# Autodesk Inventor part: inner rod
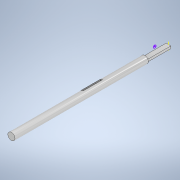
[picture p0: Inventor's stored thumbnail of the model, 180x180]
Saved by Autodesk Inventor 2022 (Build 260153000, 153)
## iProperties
Created: 2021-06
Part Number: inner rod
Material: Aluminum 6061-AHC
Document SubType Name: Modeling
Designer: adams
Density: 2.7 g/cm^3
Appearance: Aluminum - Dark
Author: adams
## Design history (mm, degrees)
sketch "Sketch1"
  geometry: 1 further point
sketch "Sketch2"
  geometry: C1 r 19.05 at (0, 0); 1 further point
  constraints: 1 centre point, 1 coincident
  dimensions: "d0" = 38.1 diameter of C1
extrude "Extrusion1" new body sketch "Sketch2" distance "d1" = 711.2; taper "d2" = 0 deg
sketch "Sketch3"
  geometry: L1 (0, 1753.937)-(0, 3144.253); L2 (0, 3144.253)-(101.6, 3144.253); L3 (101.6, 3144.253)-(101.6, 1753.937); L4 (101.6, 1753.937)-(0, 1753.937); L5 (-19.05, 0)-(-19.05, 711.2) reference; L6 (0, 225.423)-(0, 328.216); L7 (0, 328.216)-(13.075, 328.216); L8 (13.075, 328.216)-(13.075, 225.423); L9 (13.075, 225.423)-(0, 225.423); L10 (19.05, 0)-(19.05, 711.2) reference; 1 further point
  constraints: 16 end point, 6 parallel, 2 perpendicular
  dimensions: "d3" = 101.6 distance between parallel lines of L3 L1
extrude "Extrusion2" cut sketch "Sketch3" stored distance "d4" = 38.1; taper "d5" = 0 deg
sketch "Sketch5"
  geometry: L1 (-12.7, 5.842)-(12.7, 5.842); L2 (12.7, 5.842)-(12.7, -6.858); L3 (12.7, -6.858)-(-12.7, -6.858); L4 (-12.7, -6.858)-(-12.7, 5.842); C1 r 19.05 at (0, 0) reference; 1 further point
  constraints: 8 end point, 2 parallel, 1 horizontal, 1 perpendicular
  dimensions: "d11" = 25.4 distance of L1.start L1.end; "d12" = 12.7 distance of L3.end L1.start; "d13" = 6.858 distance from line of L3 C1.centre; "d14" = 12.7 distance from line of point (0, 0) L2
extrude "Extrusion4" join sketch "Sketch5" distance "d15" = 127; taper "d16" = 0 deg
sketch "Sketch6"
  geometry: L1 (0, -19.05)-(0, 19.05) reference; 1 further point
sketch "Sketch7"
  geometry: L1 (0, -19.05)-(0, 19.05) reference; 1 further point
sketch "Sketch8"
  geometry: L1 (0, 0)-(-127, 0) reference; C1 r 7.3 at (-64.936, 28.533); 1 further point
  constraints: 1 centre point
body "Solid1"
